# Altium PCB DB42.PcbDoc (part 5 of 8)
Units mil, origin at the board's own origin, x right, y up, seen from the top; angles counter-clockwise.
Board outline 3236.22 x 4456.69 mil, 8 copper layers (Top Layer, MidLayer1, MidLayer2, GND-Layer5, MidLayer3, VCC, MidLayer4, Bottom Layer), stack 62.194 mil thick; 214 components, 470 nets, 1802 pads, 1663 vias.
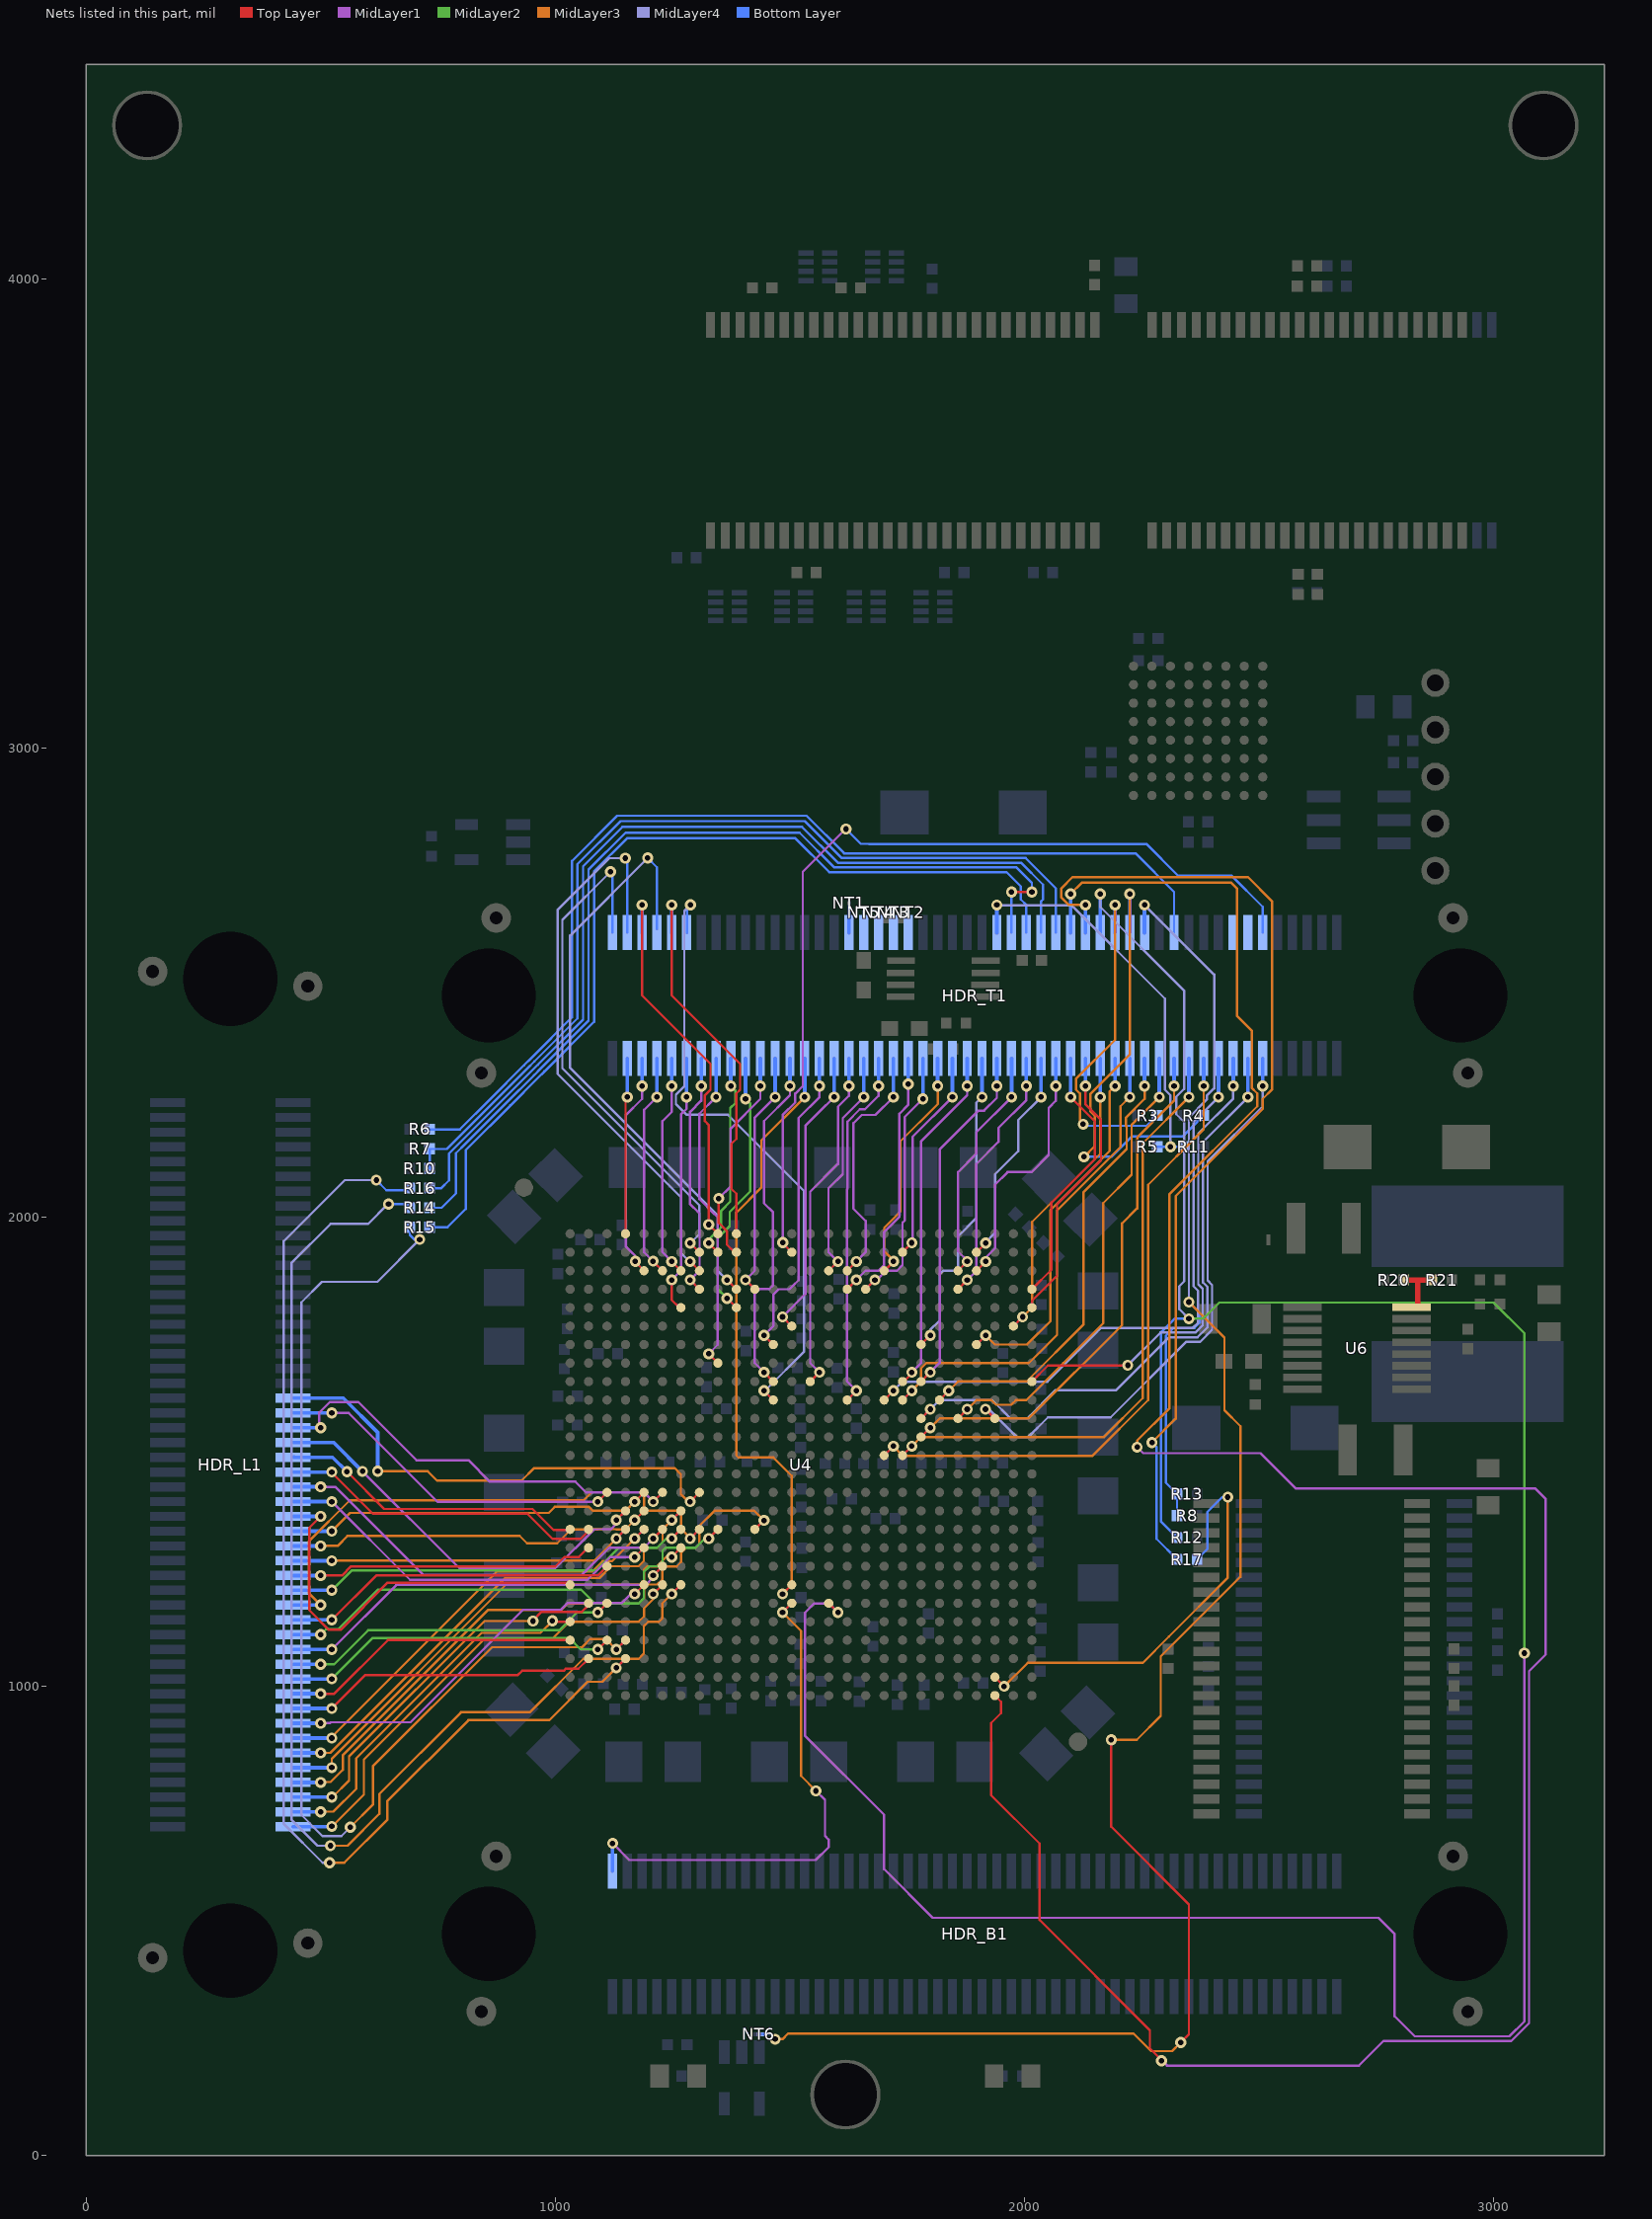
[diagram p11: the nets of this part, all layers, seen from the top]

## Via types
v1: diameter 23.62, hole 11.81, Top Layer to Bottom Layer, 1081 vias
v2: diameter 23.62, hole 11.81, Top Layer to Bottom Layer, tented both sides, 466 vias
v3: diameter 27.56, hole 15.75, Top Layer to Bottom Layer, 116 vias

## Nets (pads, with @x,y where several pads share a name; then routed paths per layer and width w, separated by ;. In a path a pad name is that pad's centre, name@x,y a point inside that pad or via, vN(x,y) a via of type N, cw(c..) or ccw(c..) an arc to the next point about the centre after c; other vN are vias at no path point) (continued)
EXTEND_B20: HDR_L1.42 U4.R8 | length 1060.6
  Top Layer w5: v1(1287.4,1393.7) U4.R8@1307.09,1413.39
  MidLayer3 w5: v2(621.34,1458.59) 727.86,1458.59 747.84,1438.61 928.18,1438.61 954.75,1465.18 1254.21,1465.18 1267.5,1451.89 1267.5,1409.73 1283.53,1393.7 v1(1287.4,1393.7)
  Bottom Layer w7.87: HDR_L1.42@440.94,1614.17 548.1,1614.17 621.34,1540.93 v2(621.34,1458.59)
EXTEND_B21: HDR_L1.44 U4.R3 | length 754.7
  Top Layer w5: v1(1090.55,1393.7) U4.R3@1110.24,1413.39
  MidLayer1 w5: v2(523.62,1582.68) 559.49,1582.68 748.86,1393.31 v1@1089.37,1393.31
  Bottom Layer w7.87: HDR_L1.44@440.94,1582.67 v2(523.62,1582.68)
EXTEND_B22: HDR_L1.46 U4.R6 | length 928.4
  Top Layer w5: v1(1208.66,1393.7) U4.R6@1228.35,1413.39
  MidLayer1 w5: v2@501.17,1553.15 496.82,1557.5 496.82,1583.43 519.29,1605.91 580.01,1605.91 704.01,1481.9 814.75,1481.9 860.53,1436.13 1043,1436.13 1065.75,1413.39 1188.18,1413.39 1188.58,1413.78 v1(1208.66,1393.7)
  Bottom Layer w7.87: HDR_L1.46@440.94,1551.18 v2(500,1551.18)
EXTEND_B23: HDR_L1.48 U4.T4 | length 875.1
  Top Layer w5: v1(1129.92,1354.33) U4.T4@1149.61,1374.02
  MidLayer1 w5: v2(589.03,1458.19) 795.58,1251.65 999.88,1251.65 1083.11,1334.87 1118.57,1334.87 1129.92,1346.23 v1(1129.92,1354.33)
  Bottom Layer w7.87: HDR_L1.48@440.94,1519.68 523.62,1519.68 527.54,1519.68 v2(589.03,1458.19)
EXTEND_B24: HDR_L1.50 U4.U1 | length 654.8
  Top Layer w5: v2(555.93,1457.41) 635.25,1378.09 951.24,1378.09 996.03,1333.3 U4.U1@1031.1,1333.3
  Bottom Layer w7.87: HDR_L1.50@440.94,1488.19 HDR_L1.50@442.07,1488.19 ; HDR_L1.50@442.41,1488.53 HDR_L1.50@442.07,1488.19 ; v2(555.93,1457.41) 525.15,1488.19 HDR_L1.50@442.07,1488.19
EXTEND_B25: HDR_L1.52 U4.U2 | length 696.2
  Top Layer w5: v2@523,1456.07 611.34,1367.72 940.73,1367.72 994.06,1314.38 1053.95,1314.38 U4.U2@1070.87,1331.3
  Bottom Layer w7.87: HDR_L1.52@440.94,1456.69 v2(523.62,1456.69)
EXTEND_B26: HDR_L1.54 U4.U6 | length 905.1
  Top Layer w5: v1(1208.66,1314.96) U4.U6@1228.35,1334.65
  MidLayer1 w5: v2(500,1425.2) 531.11,1425.2 718.48,1237.83 1057.23,1237.83 1114.87,1295.47 1189.09,1295.47 1208.58,1314.96 v1(1208.66,1314.96)
  Bottom Layer w7.87: HDR_L1.54@440.94,1425.19 v2(500,1425.2)
EXTEND_B27: HDR_L1.56 U4.V5 | length 846.1
  Top Layer w5: v1(1169.29,1275.59) U4.V5@1188.98,1295.28
  MidLayer1 w5: v2(523.62,1393.7) v2@523.75,1393.7 ; v2@523.75,1393.58 690.32,1227.01 1068.58,1227.01 1117.17,1275.59 v1(1169.29,1275.59) v1@1169.29,1274.8
  Bottom Layer w7.87: HDR_L1.56@440.94,1393.7 v2(523.62,1393.7)
EXTEND_B28: HDR_L1.58 U4.Y1 | length 885.8
  Top Layer w5: v2(500,1362.21) 475.56,1337.76 475.56,1162.3 517.32,1120.54 542.18,1120.54 642.65,1221.01 1027.03,1221.01 U4.Y1@1031.5,1216.54
  Bottom Layer w7.87: HDR_L1.58@440.94,1362.2 v2(500,1362.21)
EXTEND_B29: HDR_L1.60 U4.R5 | length 790.8
  Top Layer w5: v1(1169.29,1393.7) U4.R5@1188.98,1413.39
  MidLayer3 w5: v2@522,1331 523.62,1331 562.35,1369.73 985.97,1369.73 998.76,1382.52 1071.93,1382.52 1080.43,1374.02 1149.61,1374.02 v1(1169.29,1393.7)
  Bottom Layer w7.87: HDR_L1.60@440.94,1330.71 v2(523.62,1330.71)
EXTEND_B30: HDR_L1.62 U4.T5 | length 791.5
  Top Layer w5: v1(1169.29,1354.33) U4.T5@1188.98,1374.02
  MidLayer3 w5: v2@501.17,1299.41 535.83,1299.41 556.94,1320.53 923.98,1320.53 939.72,1304.78 1003.78,1304.78 1033.25,1334.25 1090.07,1334.25 1090.84,1335.02 1129.63,1335.02 1130.38,1334.26 1149.23,1334.26 v1(1169.29,1354.33)
  Bottom Layer w7.87: HDR_L1.62@440.94,1299.21 v2(500,1299.21)
EXTEND_B31: HDR_L1.64 U4.U4 | length 740.1
  Top Layer w5: v1(1129.92,1314.96) U4.U4@1149.61,1334.65
  MidLayer3 w5: v2(523.62,1267.72) v2@525.2,1267.72 ; v2@523.62,1269.29 524.41,1268.5 v2@525.2,1267.72 ; v1@1131.1,1315.75 1130.12,1314.76 1083.07,1267.72 v2@525.2,1267.72
  Bottom Layer w7.87: HDR_L1.64@440.94,1267.71 v2(523.62,1267.72)
EXTEND_B32: HDR_L1.66 U4.V2 | length 655.6
  Top Layer w5: v2@501.58,1237.8 v2(500,1236.22) 545.28,1236.22 564.73,1255.67 ; 564.82,1255.58 999.63,1255.58 1019.42,1275.38 1050.01,1275.38 U4.V2@1069.91,1295.28
  Bottom Layer w7.87: HDR_L1.66@440.94,1236.22 v2(500,1236.22)
EXTEND_B33: HDR_L1.68 U4.U7 | length 880.6
  Top Layer w5: v1(1248.03,1314.96) U4.U7@1267.72,1334.65
  MidLayer2 w5: v2(523.62,1204.72) 565.63,1246.73 1086.34,1246.73 1134.69,1295.08 1216.67,1295.08 1236.55,1314.96 v1(1248.03,1314.96)
  Bottom Layer w7.87: HDR_L1.68@440.94,1204.72 v2(523.62,1204.72)
EXTEND_B34: HDR_L1.70 U4.U8 | length 1160.6
  Top Layer w5: v1(1287.4,1314.96) U4.U8@1307.09,1334.65
  MidLayer3 w5: v2@499.2,1174.03 473.98,1199.25 473.98,1308.47 562.05,1396.54 1060.3,1396.54 1077.48,1413.72 1179.53,1413.72 1189.09,1404.17 1189.09,1380.18 1195,1374.27 1258.83,1374.27 1267.89,1365.21 1267.89,1335.66 v1@1287.4,1316.15
  Bottom Layer w7.87: HDR_L1.70@440.94,1173.23 v2(500,1173.23)
EXTEND_B35: HDR_L1.72 U4.W3 | length 716.6
  Top Layer w5: v2(523.62,1141.73) 618.11,1236.22 1090.55,1236.22 U4.W3@1110.24,1255.91
  Bottom Layer w7.87: HDR_L1.72@440.94,1141.73 v2(523.62,1141.73)
EXTEND_B36: HDR_L1.74 U4.U9 | length 1069.3
  Top Layer w5: v1(1326.77,1314.96) U4.U9@1346.46,1334.65
  MidLayer2 w5: v2(500,1110.24) 511.48,1121.72 537.4,1121.72 622.03,1206.34 1054.29,1206.34 1083.75,1176.88 1178.06,1176.88 1188.7,1187.52 1188.7,1243.86 1200.91,1256.07 1218.25,1256.07 1228.49,1266.32 1228.49,1289.17 1234.8,1295.47 1299.02,1295.47 1318.51,1314.96 v1(1326.77,1314.96)
  Bottom Layer w7.87: HDR_L1.74@440.94,1110.23 v2(500,1110.24)
EXTEND_B37: HDR_L1.76 U4.W6 | length 863.1
  Top Layer w5: v1(1208.66,1236.22) U4.W6@1228.35,1255.91
  MidLayer1 w5: v2(523.62,1078.74) 661.16,1216.28 1192.64,1216.28 1208.66,1232.3 v1(1208.66,1236.22)
  Bottom Layer w7.87: HDR_L1.76@440.94,1078.74 v2(523.62,1078.74)
EXTEND_B38: HDR_L1.78 U4.AA3 | length 723.1
  Top Layer w5: v1(1090.55,1157.48) U4.AA3@1110.24,1177.17
  MidLayer2 w5: v2(500,1047.25) 528.68,1047.25 600.72,1119.29 1008.57,1119.29 1046.77,1157.48 v1(1090.55,1157.48)
  Bottom Layer w7.87: HDR_L1.78@440.94,1047.24 v2(500,1047.25)
EXTEND_B39: HDR_L1.80 U4.AC3 | length 723.7
  Top Layer w5: v1(1090.55,1078.74) U4.AC3@1110.24,1098.42
  MidLayer2 w5: v2(523.62,1015.75) 610.94,1103.06 1029.54,1103.06 1053.86,1078.74 v1(1090.55,1078.74)
  Bottom Layer w7.87: HDR_L1.80@440.94,1015.74 v2(523.62,1015.75)
EXTEND_B40: HDR_L1.82 U4.AC1 | length 638.2
  Top Layer w5: v2(500,984.25) 528.74,984.25 643.19,1098.7 1003.94,1098.7 ; 1003.7,1098.42 U4.AC1@1031.5,1098.42
  Bottom Layer w7.87: HDR_L1.82@440.94,984.25 v2(500,984.25)
EXTEND_B41: HDR_L1.84 U4.AD2 | length 673
  Top Layer w5: v2(523.62,952.75) 595.17,1024.3 920.13,1024.3 929.02,1033.2 1017.85,1033.2 1022.17,1037.52 1049.29,1037.52 1070.04,1058.27 U4.AD2@1070.04,1058.5
  Bottom Layer w7.87: HDR_L1.84@440.94,952.75 v2(523.62,952.75)
EXTEND_B42: HDR_L1.86 U4.Y5 | length 873.2
  Top Layer w5: v1(1169.29,1196.85) U4.Y5@1188.98,1216.54
  MidLayer1 w5: v2(500,921.26) 499.26,922 500,922 520.28,922 521.82,923.54 ; 520.47,923.54 521.82,923.54 ; v1(1169.29,1196.85) 1161,1196.85 1141.42,1177.27 1025.58,1177.27 1011.79,1163.48 931.42,1163.48 691.47,923.54 521.82,923.54
  Bottom Layer w7.87: HDR_L1.86@440.94,921.26 v2(500,921.26)
EXTEND_B43: HDR_L1.88 U4.U5 | length 933.4
  Top Layer w5: v1(1169.29,1314.96) U4.U5@1188.98,1334.65
  MidLayer3 w5: v2@522,891 522.19,891.19 875.58,1244.58 1078.75,1244.58 1101.1,1266.93 1121.26,1266.93 v1(1169.29,1314.96)
  Bottom Layer w7.87: HDR_L1.88@440.94,889.76 v2(523.62,889.76)
EXTEND_B44: HDR_L1.90 U4.T7 | length 1070.2
  Top Layer w5: v1(1248.03,1354.33) U4.T7@1267.72,1374.02
  MidLayer3 w5: v2(500,858.27) 520.27,858.27 892.83,1230.83 1093.57,1230.83 1118.81,1256.07 1177.67,1256.07 1188.7,1267.1 1188.7,1289.17 1194.81,1295.28 1217.72,1295.28 1223.92,1301.48 1228.72,1306.28 1228.72,1335.02 v1(1248.03,1354.33)
  Bottom Layer w7.87: HDR_L1.90@440.94,858.26 v2(500,858.27)
EXTEND_B45: HDR_L1.92 U4.V7 | length 1045
  Top Layer w5: v1(1248.03,1275.59) U4.V7@1267.72,1295.28
  MidLayer3 w5: v2(523.62,826.77) 523.62,845.62 894.54,1216.54 1178.71,1216.54 1189.09,1226.92 1189.09,1249.37 1195.25,1255.53 1216.16,1255.53 1236.22,1275.59 v1(1248.03,1275.59)
  Bottom Layer w7.87: HDR_L1.92@440.94,826.77 v2(523.62,826.77)
EXTEND_B46: HDR_L1.94 U4.U11 | length 1358.1
  Top Layer w5: U4.U11@1425.2,1334.65 v1@1445.28,1354.72
  MidLayer3 w5: v2@500,796 521,796 546.84,821.84 546.84,852.84 857.09,1163.09 1012.54,1163.09 1026.33,1176.88 1179.24,1176.88 1189.09,1186.73 1189.09,1209.19 1196.81,1216.91 1217.32,1216.91 1227.97,1227.56 1227.97,1248.84 1231.92,1252.78 1234.66,1255.53 1258.66,1255.53 1268.09,1264.96 1268.09,1284.23 1279.13,1295.28 1299.21,1295.28 1306.71,1302.77 1306.71,1341.75 1338.98,1374.02 1424.41,1374.02 v1(1444.88,1353.54)
  Bottom Layer w7.87: HDR_L1.94@440.94,795.27 v2(500,795.28)
EXTEND_B47: HDR_L1.96 U4.AA2 | length 832.6
  Top Layer w5: v1@951.51,1139.84 970.49,1158.82 1056.57,1158.82 1070.87,1173.11 U4.AA2@1070.87,1177.17
  MidLayer3 w5: v2(523.62,763.78) v2@523.62,764 ; v2@525,764 560.48,799.48 560.48,850.48 849.05,1139.05 v1(952.3,1139.05)
  Bottom Layer w7.87: HDR_L1.96@440.95,763.78 v2(523.62,763.78)
EXTEND_B48: HDR_L1.98 U4.AB1 | length 795.6
  Top Layer w5: v1@995.32,1137.8 U4.AB1@1031.5,1137.8
  MidLayer3 w5: v2(500,732.28) 500.72,733 527,733 575.62,781.62 575.62,846.62 842.84,1113.84 968.06,1113.84 v1(993.67,1139.45)
  Bottom Layer w7.87: HDR_L1.98@440.94,732.28 v2(500,732.28)
EXTEND_B49: HDR_L1.100 U4.Y6 | length 1061.2
  Top Layer w5: v1(1208.66,1196.85) U4.Y6@1228.35,1216.54
  MidLayer3 w5: v1@523.62,700.79 523.96,701.12 592.02,769.18 592.02,844.02 847.61,1099.61 991.73,1099.61 1029.92,1137.79 1177.56,1137.79 1188.98,1149.21 1188.98,1166.24 1208.66,1185.92 v1(1208.66,1196.85)
  Bottom Layer w7.87: HDR_L1.100@440.94,700.78 523.49,700.79 v1@523.62,700.79
  other v1: 523.49,701.59
EXTEND_C0: HDR_T1.89 U4.L24 | length 1260.8
  Top Layer w5: v1(1916.93,1590.55) 1936.61,1570.87 U4.L24@1937.01,1570.87
  MidLayer4 w5: v1@1917.32,1589.37 1925.2,1589.37 1983.07,1531.5 2008.27,1531.5 2050,1573.23 2183.47,1573.23 2344.24,1734 2374,1734 2400,1760 2400,1855.43 2390.39,1865.03 2390.39,2118.74 2507.87,2236.22 v2(2507.87,2279.53)
  Bottom Layer w7.87: v2(2507.87,2279.53) HDR_T1.89@2507.88,2338.58
EXTEND_C1: HDR_T1.87 U4.L20 | length 1340.8
  Top Layer w5: U4.L20@1779.53,1570.87 v1(1799.21,1590.55)
  MidLayer4 w5: v1(1799.21,1590.55) 1818.9,1610.24 1931.1,1610.24 1970.47,1570.87 2005.91,1570.87 2066.54,1631.5 2195.67,1631.5 2308.17,1744 2369,1744 2390,1765 2390,1851.28 2380.39,1860.89 2380.39,2159.92 v2(2476.38,2255.9)
  Bottom Layer w7.87: v2(2476.38,2255.9) HDR_T1.87@2476.38,2338.58
EXTEND_C2: HDR_T1.85 U4.J26 | length 1017.6
  Top Layer w5: U4.J26@2015.75,1649.61 2050,1683.86 2219.68,1683.86 v1(2220.08,1684.25)
  MidLayer4 w5: v1(2220.08,1684.25) 2289.83,1754 2364.14,1754 2380,1769.86 2380,1847.14 2370.39,1856.75 2370.39,2178.39 2444.88,2252.88 v2(2444.88,2279.53)
  Bottom Layer w7.87: v2(2444.88,2279.53) HDR_T1.85@2444.88,2338.58
EXTEND_C3: HDR_T1.83 U4.K18 | length 1327
  Top Layer w5: U4.K18@1700.79,1610.24 v1(1720.47,1629.92)
  MidLayer4 w5: v1(1720.47,1629.92) 1739.84,1649.28 2048.89,1649.28 2163.61,1764 2359,1764 2370,1775 2370,1843 2360.39,1852.61 2360.39,2202.92 v2(2413.38,2255.9)
  Bottom Layer w7.87: v2(2413.38,2255.9) HDR_T1.83@2413.39,2338.58
EXTEND_C4: HDR_T1.81 U4.N18 | length 1406.5
  Top Layer w5: U4.N18@1700.79,1492.13 v1(1720.47,1511.81)
  MidLayer3 w5: v1(1720.47,1511.81) 1741.34,1490.94 2144.49,1490.94 2263.78,1610.24 2263.78,2068.95 2381.89,2187.05 v2(2381.89,2279.53)
  Bottom Layer w7.87: v2(2381.89,2279.53) HDR_T1.81@2381.89,2338.58
EXTEND_C5: HDR_T1.79 U4.N19 | length 1327.5
  Top Layer w5: U4.N19@1740.16,1492.13 v1(1759.84,1511.81)
  MidLayer3 w5: v1(1759.84,1511.81) 1779.53,1531.5 2169.29,1531.5 2251.97,1614.17 2251.97,2157.48 v2(2350.39,2255.9)
  Bottom Layer w7.87: v2(2350.39,2255.9) HDR_T1.79@2350.4,2338.58
EXTEND_C6: HDR_T1.77 U4.M20 | length 1141.7
  Top Layer w5: U4.M20@1779.53,1531.5 v1(1799.21,1551.18)
  MidLayer3 w5: v1(1799.21,1551.18) 1818.9,1570.87 2008.75,1570.87 2208.1,1770.22 2208.1,1986.7 2240.16,2018.76 2240.16,2169.29 2318.89,2248.03 v2(2318.89,2279.53)
  Bottom Layer w7.87: v2(2318.89,2279.53) HDR_T1.77@2318.9,2338.58
EXTEND_C7: HDR_T1.75 U4.L22 | length 1016.2
  Top Layer w5: U4.L22@1858.27,1570.87 v1(1877.95,1590.55)
  MidLayer3 w5: v1(1877.95,1590.55) 1897.64,1610.24 1929.13,1610.24 1939.37,1600 1971.65,1600 1981.89,1610.24 2003.93,1610.24 2082.83,1689.13 2167.75,1774.05 2167.75,2029.99 2228.35,2090.59 2228.35,2196.85 v2(2287.4,2255.9)
  Bottom Layer w7.87: v2(2287.4,2255.9) HDR_T1.75@2287.4,2338.58
EXTEND_C8: HDR_T1.73 U4.K21 | length 995.5
  Top Layer w5: U4.K21@1818.9,1610.24 v1(1838.58,1629.92)
  MidLayer3 w5: v1(1838.58,1629.92) 1858.64,1649.98 2004.7,1649.98 2125.44,1770.72 2125.44,2052.62 2217.94,2145.12 2217.94,2194.32 ; 2216.54,2194.32 2216.54,2212.6 2255.9,2251.97 v2(2255.9,2279.53)
  Bottom Layer w7.87: v2(2255.9,2279.53) HDR_T1.73@2255.91,2338.58
EXTEND_C9: HDR_T1.71 U4.K19 | length 1057.1
  Top Layer w5: U4.K19@1740.16,1610.24 v1(1759.84,1629.92)
  MidLayer3 w5: v1(1759.84,1629.92) 1779.15,1649.23 1779.15,1677.58 1790.55,1688.98 2009.33,1688.98 2069.35,1749 2069.35,2014.25 2204.72,2149.62 2204.72,2236.22 v2(2224.41,2255.9)
  Bottom Layer w7.87: v2(2224.41,2255.9) HDR_T1.71@2224.41,2338.58
EXTEND_C10: HDR_T1.69 U4.G23 | length 811.9
  Top Layer w5: U4.G23@1897.64,1728.35 v1(1917.32,1748.03)
  MidLayer3 w5: v1(1917.32,1748.03) 1937.01,1728.35 2005.3,1728.35 2055.21,1778.25 2055.21,2014.74 2181.5,2141.02 2181.5,2268.11 v2(2192.91,2279.53)
  Bottom Layer w7.87: v2(2192.91,2279.53) HDR_T1.69@2192.91,2338.58
EXTEND_C11: HDR_T1.67 U4.F25 | length 647.5
  Top Layer w5: U4.F25@1976.38,1767.72 v1(1996.06,1787.4)
  MidLayer3 w5: v1(1996.06,1787.4) 2010.23,1801.56 2016.22,1807.55 2016.22,1990.14 2161.42,2135.34 v2(2161.42,2255.9)
  Bottom Layer w7.87: v2(2161.42,2255.9) HDR_T1.67@2161.42,2338.58
EXTEND_C12: HDR_T1.65 U4.E26 | length 605.3
  Top Layer w5: U4.E26@2015.75,1807.09 2015.75,1821.65 2069.38,1875.29 2069.38,2027.07 2163,2120.69 2163,2207.25 2129.57,2240.68 ; 2129.92,2241.76 v2(2129.92,2279.53)
  Bottom Layer w7.87: v2(2129.92,2279.53) HDR_T1.65@2129.92,2338.58
EXTEND_C13: HDR_T1.63 U4.D26 | length 569.1
  Top Layer w5: U4.D26@2015.75,1846.46 2057.31,1888.02 2057.31,2030.74 2150,2123.43 2150,2204.33 v2(2098.42,2255.9)
  Bottom Layer w7.87: v2(2098.42,2255.9) HDR_T1.63@2098.43,2338.58
EXTEND_C14: HDR_T1.61 U4.C23 | length 552.9
  Top Layer w5: U4.C23@1897.64,1885.83 v1(1917.32,1905.51)
  MidLayer1 w5: v1(1917.32,1905.51) 1917.32,1913.78 1937.38,1933.84 1937.38,2069.35 1963.95,2095.92 2015.23,2095.92 2051.64,2132.33 2051.64,2232.74 2066.93,2248.03 v2(2066.93,2279.53)
  Bottom Layer w7.87: v2(2066.93,2279.53) HDR_T1.61@2066.93,2338.58
EXTEND_C15: HDR_T1.59 U4.B23 | length 470.5
  Top Layer w5: U4.B23@1897.64,1925.2 v1(1917.32,1944.88)
  MidLayer4 w5: v1(1917.32,1944.88) 1917.32,1946.46 1937.01,1966.14 1937.01,2091 1986.7,2140.69 1986.7,2207.17 v2(2035.43,2255.9)
  Bottom Layer w7.87: v2(2035.43,2255.9) HDR_T1.59@2035.43,2338.58
EXTEND_C16: HDR_T1.57 U4.D22 | length 552.5
  Top Layer w5: U4.D22@1858.27,1846.46 v1(1877.95,1866.14)
  MidLayer1 w5: v1(1877.95,1866.14) 1897.26,1885.45 1897.26,2113.26 1944.35,2160.35 1944.35,2189.84 2003.93,2249.42 v2(2003.93,2279.53)
  Bottom Layer w7.87: v2(2003.93,2279.53) HDR_T1.57@2003.94,2338.58
EXTEND_C17: HDR_T1.55 U4.C22 | length 516.8
  Top Layer w5: U4.C22@1858.27,1885.83 v1(1877.95,1905.51)
  MidLayer1 w5: v1@1878.74,1905.91 1878.74,1906.3 1858.27,1926.77 1858.27,1985.83 1858.27,2096 1897,2134.73 1897,2180.47 ; 1897,2181 1897,2180.47 ; v2(1972.44,2255.9) 1897,2180.47
  Bottom Layer w7.87: v2(1972.44,2255.9) HDR_T1.55@1972.44,2338.58
EXTEND_C18: HDR_T1.53 U4.J20 | length 762.8
  Top Layer w5: U4.J20@1779.53,1649.61 v1(1799.21,1669.29)
  MidLayer1 w5: v1(1799.21,1669.29) 1819.27,1689.35 1819.27,2144.27 1902,2227 1913.94,2227 1940.94,2254 v2(1940.94,2279.53)
  Bottom Layer w7.87: v2(1940.94,2279.53) HDR_T1.53@1940.95,2338.58
EXTEND_C19: HDR_T1.51 U4.G20 | length 677.7
  Top Layer w5: U4.G20@1779.53,1728.35 v1(1799.21,1748.03)
  MidLayer4 w5: v1(1799.21,1748.03) 1799.21,1759.94 1818.9,1779.63 1818.9,1878.35 1826.38,1885.83 1849.61,1885.83 1858.27,1894.49 1858.27,1959 1897.04,1997.78 1897.04,2243.5 v2(1909.45,2255.9)
  Bottom Layer w7.87: v2(1909.45,2255.9) HDR_T1.51@1909.45,2338.58
EXTEND_C20: HDR_T1.49 U4.J19 | length 746.1
  Top Layer w5: U4.J19@1746.82,1654.06 1760.95,1668.19 v1@1766.51,1673.74
  MidLayer1 w5: v1(1759.84,1669.29) 1779.15,1688.6 1779.15,2161.05 1791.5,2173.4 1877.95,2259.84 v2(1877.95,2279.53)
  Bottom Layer w7.87: v2(1877.95,2279.53) HDR_T1.49@1877.95,2338.58
EXTEND_C21: HDR_T1.47 U4.B19 | length 455.9
  Top Layer w5: U4.B19@1740.16,1925.2 v1(1759.84,1945.28)
  MidLayer1 w5: v1@1761.42,1946.06 1761.42,2170.87 v2(1846.46,2255.9)
  Bottom Layer w7.87: v2(1846.46,2255.9) HDR_T1.47@1846.46,2338.58
EXTEND_C22: HDR_T1.45 U4.C18 | length 510.4
  Top Layer w5: U4.C18@1706.3,1887.8 1706.3,1890.55 v1@1720.87,1905.51
  MidLayer3 w5: v1@1720.87,1907.48 1700.98,1927.36 1700.98,1977.36 1735.43,2011.81 1735.43,2161.43 1815.18,2241.18 1815.18,2279.3 v2(1814.96,2279.53)
  Bottom Layer w7.87: v2(1814.96,2279.53) HDR_T1.45@1814.96,2338.58
  other v1: 1720.87,1905.91
EXTEND_C23: HDR_T1.43 U4.D17 | length 558.8
  Top Layer w5: U4.D17@1661.42,1846.46 v1(1681.1,1866.14)
  MidLayer1 w5: v1(1681.1,1866.14) 1685.04,1866.14 1704.72,1885.83 1728.35,1885.83 1740.18,1897.66 1740.18,1988.17 ; 1740.16,1988.19 1744.88,1992.91 1744.88,2213.38 v2(1783.46,2251.96)
  Bottom Layer w7.87: v2(1783.46,2251.96) HDR_T1.43@1783.47,2338.58
EXTEND_C24: HDR_T1.41 U4.D16 | length 561.9
  Top Layer w5: U4.D16@1622.05,1846.46 v1(1641.73,1866.14)
  MidLayer1 w5: v1(1641.73,1866.14) 1661.42,1885.83 1688.73,1885.83 1700.81,1897.91 1700.81,1968.52 1733.46,2001.18 1733.46,2047.64 1733.46,2220.46 1751.97,2238.97 v2@1751.97,2279.53
  Bottom Layer w7.87: v2@1751.97,2279.53 HDR_T1.41@1751.97,2338.58
  other v2: 1751.97,2283.46
EXTEND_C25: HDR_T1.39 U4.C16 | length 533
  Top Layer w5: U4.C16@1622.05,1885.83 v1(1641.73,1905.51)
  MidLayer1 w5: v1(1641.73,1905.51) 1661.42,1925.2 1661.42,1992.13 1635.43,2018.11 1635.43,2200.25 1653.12,2217.94 1682.5,2217.94 v2(1720.47,2255.9)
  MidLayer3 w5: v1@1640.55,1905.91 v1@1641.34,1905.91
  Bottom Layer w7.87: v2(1720.47,2255.9) HDR_T1.39@1720.47,2338.58
EXTEND_C26: HDR_T1.37 U4.K16 | length 779.3
  Top Layer w5: U4.K16@1622.05,1610.24 v1(1641.73,1629.92)
  MidLayer1 w5: 1621.61,1982.63 1622.05,1983.07 ; v1(1641.73,1629.92) 1622.05,1649.61 1622.05,1983.07 ; v2(1688.97,2279.53) 1688.98,2258.71 1660.01,2229.74 1649.18,2229.74 1622.83,2203.39 1622.83,2059.84 1622.05,2059.06 1622.05,1983.07
  Bottom Layer w7.87: v2(1688.97,2279.53) HDR_T1.37@1688.98,2338.58
EXTEND_C27: HDR_T1.35 U4.C15 | length 500.4
  Top Layer w5: U4.C15@1582.68,1885.83 v1(1602.36,1905.51)
  MidLayer1 w5: v1(1602.36,1905.51) 1582.3,1925.57 1582.3,2061.44 1612.6,2091.73 1612.6,2211.02 v2(1657.48,2255.9)
  Bottom Layer w7.87: v2(1657.48,2255.9) HDR_T1.35@1657.48,2338.58
EXTEND_C28: HDR_T1.33 U4.J14 | length 739.5
  Top Layer w5: U4.J14@1543.31,1649.61 v1(1562.99,1669.29)
  MidLayer1 w5: v1(1562.99,1669.29) 1543.31,1688.98 1543.31,2054.33 1602.36,2113.39 1602.36,2235.07 1625.98,2258.69 v2(1625.98,2279.53)
  Bottom Layer w7.87: v2(1625.98,2279.53) HDR_T1.33@1625.99,2338.58
EXTEND_C29: HDR_T1.31 U4.F13 | length 624.8
  Top Layer w5: v1(1484.25,1787.4) U4.F13@1503.94,1767.72
  MidLayer1 w5: v1(1484.25,1787.4) 1533.07,1836.22 1533.07,2194.88 1576.77,2238.58 ; 1576.97,2238.39 v2(1594.49,2255.9)
  Bottom Layer w7.87: v2(1594.49,2255.9) HDR_T1.31@1594.49,2338.58
EXTEND_C30: HDR_T1.29 U4.G12 | length 680.9
  Top Layer w5: v1(1444.88,1748.03) U4.G12@1464.57,1728.35
  MidLayer1 w5: v1(1444.88,1748.03) 1464.57,1767.72 1464.57,1835.04 1475.98,1846.46 1499.21,1846.46 1506.46,1853.7 1518.5,1865.75 1518.5,2211.42 1562.99,2255.9 v2(1562.99,2279.53)
  Bottom Layer w7.87: v2(1562.99,2279.53) HDR_T1.29@1562.99,2338.58
EXTEND_C31: HDR_T1.27 U4.Y13 | length 1330.5
  Top Layer w5: v1(1484.25,1196.85) U4.Y13@1503.94,1216.54
  MidLayer3 w5: v1(1484.25,1196.85) 1503.94,1216.54 1503.94,1448.82 1464.57,1488.19 1389.76,1488.19 1386.2,1491.75 1386.2,2009.85 1439.13,2062.79 1439.13,2163.54 v2(1531.5,2255.9)
  Bottom Layer w7.87: v2(1531.5,2255.9) HDR_T1.27@1531.5,2338.58
EXTEND_C32: HDR_T1.25 U4.J12 | length 764.3
  Top Layer w5: v1(1444.88,1669.29) U4.J12@1464.57,1649.61
  MidLayer1 w5: v1(1444.88,1669.29) 1424.82,1689.35 1424.82,1835.45 1436.2,1846.83 1456.28,1846.83 1464.19,1854.74 1464.19,2010.22 1444.88,2029.53 1444.88,2204.72 1500,2259.84 v2(1500,2279.53)
  Bottom Layer w7.87: v2(1500,2279.53) HDR_T1.25@1500,2338.58
EXTEND_C33: HDR_T1.23 U4.D11 | length 526.4
  Top Layer w5: v1(1405.51,1866.14) U4.D11@1425.2,1846.46
  MidLayer1 w5: v1(1405.51,1866.14) 1425.2,1885.83 1425.2,2212.6 v2(1468.5,2255.9)
  Bottom Layer w7.87: v2(1468.5,2255.9) HDR_T1.23@1468.5,2338.58
EXTEND_C34: HDR_T1.21 U4.B10 | length 466.1
  Top Layer w5: v1(1348.43,2039.76) 1348.43,1987.83 1365.75,1970.5 1365.75,1941.73 1382.28,1925.2 U4.B10@1385.83,1925.2
  MidLayer1 w5: v1@1349.21,2040.94 1373.62,2065.35 1373.62,2188.58 1437.01,2251.97 v2(1437.01,2279.53)
  Bottom Layer w7.87: v2(1437.01,2279.53) HDR_T1.21@1437.01,2338.58
EXTEND_C35: HDR_T1.19 U4.E10 | length 577
  Top Layer w5: v1(1366.14,1826.77) U4.E10@1385.83,1807.09
  MidLayer2 w5: v1(1366.14,1826.77) 1346.26,1846.65 1346.26,1955.31 1371.65,1980.71 1371.65,2011.02 1415.75,2055.12 1415.75,2241.73 v2(1405.51,2251.97)
  Bottom Layer w7.87: v2@1405.51,2255.9 HDR_T1.19@1405.51,2338.58
EXTEND_C36: HDR_T1.17 U4.B9 | length 449.3
  Top Layer w5: v1(1326.77,1944.88) U4.B9@1346.46,1925.2
  MidLayer2 w5: v1(1326.77,1944.88) 1326.77,1951.57 1353.54,1978.35 1353.54,2013.78 1372.83,2033.07 1372.83,2232.28 1383.86,2243.31 1383.86,2269.68 v2(1374.02,2279.53)
  Bottom Layer w7.87: v2(1374.02,2279.53) HDR_T1.17@1374.02,2338.58
EXTEND_C37: HDR_T1.15 U4.H9 | length 696.7
  Top Layer w5: v1(1326.77,1708.66) U4.H9@1346.46,1688.98
  MidLayer1 w5: v1(1326.77,1708.66) 1346.08,1727.97 1346.08,1999.98 1339.37,2006.69 ; 1339.17,2006.5 1307.09,2038.58 1307.09,2220.47 v2(1342.52,2255.9)
  Bottom Layer w7.87: v2(1342.52,2255.9) HDR_T1.15@1342.52,2338.58
EXTEND_C38: HDR_T1.13 U4.D8 | length 526.8
  Top Layer w5: v1(1287.4,1866.14) U4.D8@1307.09,1846.46
  MidLayer1 w5: v1(1287.4,1866.14) 1307.46,1886.2 1307.46,2007.89 1303.94,2011.42 ; 1303.74,2011.22 1287.4,2027.56 1287.4,2224.41 1311.02,2248.03 v2(1311.02,2279.53)
  Bottom Layer w7.87: v2(1311.02,2279.53) HDR_T1.13@1311.02,2338.58
EXTEND_C39: HDR_T1.11 U4.E7 | length 554.8
  Top Layer w5: v1(1248.03,1866.14) 1248.03,1823.23 1264.17,1807.09 U4.E7@1267.72,1807.09
  MidLayer1 w5: v1(1248.03,1866.14) 1267.72,1885.83 1267.72,2218.87 1279.53,2230.68 v2(1279.53,2255.9)
  Bottom Layer w7.87: v2(1279.53,2255.9) HDR_T1.11@1279.53,2338.58
EXTEND_C40: HDR_T1.12 U4.K12 | length 1334.6
  Top Layer w5: v1(1444.88,1629.92) U4.K12@1464.57,1610.24
  MidLayer4 w5: v2(1288.19,2665.75) 1274.8,2652.36 1274.8,2278.74 1257.09,2261.02 1257.09,2240.94 1279.89,2218.14 1368.11,2218.14 1529.92,2056.33 1529.92,1712.99 1451.18,1634.25 v1@1449.21,1634.25
  Bottom Layer w5: HDR_T1.12@1280.31,2605.91 1280.31,2606.3 1280.31,2657.87 v2(1288.19,2665.75)
EXTEND_C41: HDR_T1.9 U4.C7 | length 477.2
  Top Layer w5: v1(1248.03,1905.51) U4.C7@1267.72,1885.83
  MidLayer1 w5: v1(1248.03,1905.51) 1228.35,1925.2 1228.35,2204.72 1248.03,2224.41 v2(1248.03,2279.53)
  Bottom Layer w7.87: v2(1248.03,2279.53) HDR_T1.9@1248.03,2338.58
EXTEND_C42: HDR_T1.10 U4.A10 | length 831.9
  Top Layer w5: v2(1248.03,2665.35) 1248.03,2472.44 1393.7,2326.78 1393.7,2271.65 1385.83,2263.78 1385.83,2166.96 1375.59,2156.72 1375.59,2060.24 1385.83,2050 U4.A10@1385.83,1964.57
  Bottom Layer w7.87: HDR_T1.10@1248.03,2606.3 v2(1248.03,2665.35)
EXTEND_C43: HDR_T1.7 U4.C6 | length 480.2
  Top Layer w5: v1@1208.66,1905.51 U4.C6@1228.35,1885.83
  MidLayer1 w5: v1@1208.66,1905.51 1208.2,1905.97 1189.35,1924.82 1189.35,2228.72 v2(1216.54,2255.9)
  Bottom Layer w7.87: v2(1216.54,2255.9) HDR_T1.7@1216.54,2338.58
  other v1: 1208.4,1906.17
EXTEND_C44: HDR_T1.8 U4.D10 | length 1295.1
  Top Layer w5: v1(1366.14,1866.14) U4.D10@1385.83,1846.46
  MidLayer4 w5: v1(1196.85,2765.35) 1197.24,2764.96 1196.85,2764.96 1196.46,2764.96 1031.5,2600 1031.5,2318.11 1346.46,2003.15 1346.46,1885.43 1365.94,1865.95 v1@1366.14,1865.75
  Bottom Layer w5: v1(1196.85,2765.35) 1216.54,2745.67 HDR_T1.8@1216.54,2613.78
EXTEND_C45: HDR_T1.5 U4.C5 | length 483
  Top Layer w5: v1@1169.68,1905.12 U4.C5@1188.98,1885.83
  MidLayer1 w5: v1(1170.47,1905.91) 1169.39,1906.99 1169.39,1918.4 1164.55,1923.25 1149.98,1937.82 1149.98,1945.34 1149.98,2216.91 1185.04,2251.97 v2(1185.04,2279.53)
  Bottom Layer w7.87: v2(1185.04,2279.53) HDR_T1.5@1185.04,2338.58
EXTEND_C46: HDR_T1.6 U4.A9 | length 895.5
  Top Layer w5: v2(1185.04,2665.35) 1185.04,2472.44 1330.71,2326.77 1330.71,2271.65 1318.9,2259.84 1318.9,2204.72 1326.77,2196.85 v1(1326.77,1984.25) U4.A9@1346.46,1964.57
  Bottom Layer w7.87: HDR_T1.6@1185.04,2606.3 v2(1185.04,2665.35) HDR_T1.6@1185.04,2606.3
EXTEND_C47: HDR_T1.3 U4.A4 | length 375.6
  Top Layer w5: U4.A4@1149.61,1964.57 1149.61,2251.97 v2(1153.54,2255.9)
  Bottom Layer w7.87: v2(1153.54,2255.9) HDR_T1.3@1153.54,2338.58
EXTEND_C48: HDR_T1.4 U4.C8 | length 1242.8
  Top Layer w5: v1(1287.4,1905.51) U4.C8@1307.09,1885.83
  MidLayer4 w5: v1(1149.21,2764.96) 1114.96,2764.96 1004.72,2654.72 1004.72,2305.51 1267.72,2042.52 1267.72,1923.62 1273.86,1917.48 v1@1284.93,1906.41
  Bottom Layer w5: v1(1149.21,2764.96) 1153.54,2760.63 HDR_T1.4@1153.54,2606.3
EXTEND_C49: HDR_T1.2 U4.B8 | length 1116.2
  Top Layer w5: v1(1287.4,1944.88) U4.B8@1307.09,1925.2
  MidLayer4 w5: v1(1117.72,2736.22) 1014.96,2633.46 1014.96,2317.32 1307.09,2025.2 1307.09,1963.78 v1@1288.19,1944.88
  Bottom Layer w5: HDR_T1.2@1122.05,2606.3 v1@1122.05,2731.89
FB: R20.2 R21.1 U6.8 | length 120.2
  Top Layer w7.87: U6.8@2842.51,1807.09 U6.8@2842.51,1808.25
  Top Layer w11.81: R20.2@2808.58,1866.14 2838.58,1866.14 ; U6.8@2838.58,1807.09 2838.58,1808.25 2838.58,1866.14 ; R21.1@2868.58,1866.14 2838.58,1866.14
FPGA_CCLK: HDR_T1.66 R17.1 | length 2147.2
  MidLayer3 w5: v2(2129.92,2665.35) 2094.49,2665.35 2078.74,2681.1 2078.74,2700.79 2102.36,2724.41 2476.38,2724.41 2527.56,2673.23 2527.56,2271.65 2507.87,2251.97 2507.87,2230.39 2322.33,2044.84 2322.33,1570.36 v1(2271.65,1519.68)
  Bottom Layer w5: v1(2271.65,1519.68) 2281.34,1510 2281.34,1314.39 R17.1@2325.28,1270.45
  Bottom Layer w7.87: HDR_T1.66@2129.92,2606.3 v2(2129.92,2665.35)
FPGA_CCLK#: R17.2 U4.AE24 | length 939.7
  Top Layer w5: U4.AE24@1936.57,1019.68 U4.AE24@1937.01,1019.68 v1(1956.69,1000)
  MidLayer3 w5: v1(1956.69,1000) 2006.69,1050 2251.97,1050 2307.84,1105.87 2433.4,1231.43 v1(2433.4,1403.2)
  Bottom Layer w5: R17.2@2367.64,1270.45 2390,1292.81 2390,1371.85 2421.35,1403.2 v1(2433.4,1403.2)
FPGA_CLK: HDR_B1.2 U4.AA13 | length 1114.4
  Top Layer w5: v1(1484.25,1157.48) U4.AA13@1503.94,1177.17
  MidLayer1 w5: v2(1122.05,665.35) 1157.48,629.92 1555.12,629.92 1582.68,657.48 1582.68,673.23 1574.8,681.1 1574.8,757.87 v1(1555.51,777.17)
  MidLayer3 w5: v1(1484.25,1157.48) 1523.62,1118.11 1523.62,809.06 v1(1555.51,777.17)
  Bottom Layer w7.87: HDR_B1.2@1122.05,606.3 v2(1122.05,665.35)
FPGA_CLK1: HDR_T1.90 U4.B13 | length 1978.2
  Top Layer w5: v1@1484.25,1944.88 U4.B13@1503.94,1925.2
  MidLayer1 w5: v1(1484.65,1945.67) 1484.65,2217.72 1511.42,2244.49 1511.42,2263.39 1527.56,2279.53 1527.56,2736.22 v1@1619.68,2828.35
  Bottom Layer w5: v1(1619.68,2827.17) 1651.18,2795.67 1669.29,2795.67 ; 1669.29,2795.28 2259.84,2795.28 2326.77,2728.35 2440.94,2728.35 2507.87,2661.42 HDR_T1.90@2507.88,2606.3
FPGA_DIN: HDR_T1.64 U4.AF24 | length 5581.6
  Top Layer w5: U4.AF24@1937.01,979.92 1950,966.93 1950,943 1929,922 1929,768 2032,665 2032,502.32 2267.32,267 2267.32,228.35 v1@2292.13,203.54
  MidLayer1 w5: v1(2240.16,1509.84) 2253,1497 2503,1497 2578,1422 3088,1422 3111,1399 3111,1068 3075.4,1032.4 3075.4,281.86 3037.54,244 2765.26,244 2712.99,191.73 2303.94,191.73 2292.91,202.76 v1@2292.13,203.54
  MidLayer3 w5: v2(2098.42,2688.98) 2122.05,2712.6 2440.94,2712.6 2452.76,2700.79 2452.76,2429.13 2484.25,2397.64 2484.25,2275.59 2496.06,2263.78 2496.06,2236.29 2309.21,2049.44 2309.21,1592.68 2240.16,1523.62 v1(2240.16,1509.84)
  Bottom Layer w7.87: v2(2098.42,2688.98) HDR_T1.64@2098.43,2606.3
  other v1: 2292.13,201.97
FPGA_DONE: HDR_T1.74 NT6.2 R8.1 R13.1 | length 4291.3
  Top Layer w5: v1(2185.04,885.83) 2185.04,700.79 2350.39,535.43 2350.39,258.27 v1(2333.07,240.94)
  MidLayer3 w5: v1(1468.5,248.03) 1484.25,248.03 1496.06,259.84 2232.68,259.84 2270.08,222.44 2314.57,222.44 v1(2333.07,240.94) ; v1@2183.86,886.22 v1@2185.04,886.22 ; v1(2185.04,885.83) v1@2185.04,886.22 ; v1(2350.39,1818.9) 2426.3,1742.99 2426.3,1588.19 2460.24,1554.25 2460.24,1233.71 2290.31,1063.78 2290.31,937.16 2239.37,886.22 v1@2185.04,886.22
  MidLayer4 w5: v2(2255.9,2665.35) 2404.33,2516.93 2404.33,2274.41 2388.58,2258.66 2388.58,2250.39 2350.39,2212.2 v1(2350.39,1818.9)
  Bottom Layer w5: NT6.2@1440.94,258.86 1457.68,258.86 v1(1468.5,248.03) ; R8.1@2325.28,1363.63 R13.1@2325.28,1410.21 2301.34,1434.15 2301.34,1747.44 2318,1764.1 2362.62,1764.1 2374.02,1775.5 2374.02,1795.28 v1(2350.39,1818.9)
  Bottom Layer w7.87: HDR_T1.74@2255.91,2606.3 v2(2255.9,2665.35)
FPGA_ID0: HDR_T1.42 NT2.1
FPGA_ID1: HDR_T1.40 NT3.1
FPGA_ID2: HDR_T1.38 NT4.1
FPGA_ID3: HDR_T1.36 NT5.1
FPGA_INIT: HDR_T1.68 R12.1 U4.AA15 | length 6193.8
  Top Layer w5: U4.AA15@1582.68,1177.17 v1(1602.36,1157.48)
  MidLayer1 w5: v1(1602.36,1157.48) 1583.05,1176.79 1551.99,1176.79 1531.89,1156.69 1531.89,895.08 1700.86,726.11 1700.86,610.17 1804.29,506.73 2754.27,506.73 2789.1,471.9 2789.1,296.9 2832,254 3033.4,254 3065.4,286 v1(3065.4,1070.7)
  MidLayer2 w5: v1(2350.39,1783.46) 2380.46,1783.46 2415,1818 3000,1818 3065.4,1752.6 v1(3065.4,1070.7)
  MidLayer4 w5: v2(2161.42,2688.98) 2161.42,2661.42 2340.16,2482.68 2340.16,2273.23 2323.62,2256.69 2323.62,2219.29 2340.39,2202.52 2340.39,1863.31 2329.8,1852.71 2329.8,1804.06 v1(2350.39,1783.46)
  Bottom Layer w5: R12.1@2325.28,1317.04 2291.34,1350.97 2291.34,1754.94 2319.86,1783.46 v1(2350.39,1783.46)
  Bottom Layer w7.87: HDR_T1.68@2161.42,2606.3 v2(2161.42,2688.98)
FPGA_INSTALLED: HDR_T1.34 NT1.1 | length 55.2
  Bottom Layer w7.87: HDR_T1.34@1625.99,2606.3 NT1.1@1625.98,2661.42
FPGA_M0: HDR_T1.60 R16.1 | length 2005.7
  Bottom Layer w5: R16.1@732.11,2061.94 757.15,2061.94 773.42,2078.21 773.42,2135.58 804.56,2166.71 884.14,2246.28 947.59,2309.74 962.63,2324.78 1059.06,2421.21 1059.06,2747.64 1142.91,2831.5 1525.98,2831.5 1602.2,2755.28 1992.76,2755.28 2039.37,2708.66 2039.37,2677.17 2035.43,2673.23 HDR_T1.60@2035.43,2606.3
FPGA_M0#: R16.2 U4.AD4 | length 2541.3
  Top Layer w5: v1(1129.92,1039.37) U4.AD4@1149.61,1059.05
  MidLayer3 w5: v1(518.57,623.86) 550.06,623.86 641.57,715.37 641.57,754.73 814.75,927.91 986.95,927.91 1068.62,1009.58 1100.14,1009.58 v1(1129.92,1039.37)
  MidLayer4 w5: v1(518.57,623.86) 503.92,623.86 421.26,706.51 421.26,1948.82 551.34,2078.9 v1(618.5,2078.9)
  Bottom Layer w5: v1(618.5,2078.9) 639.92,2057.48 685.29,2057.48 R16.2@689.74,2061.94
FPGA_M1: HDR_T1.58 R15.1 | length 2011.1
  Bottom Layer w5: R15.1@731.81,1978.35 R15.1@732.11,1978.35 769.99,1978.35 808.85,2017.2 808.85,2142.71 812.84,2146.71 904.14,2237.99 ; 904.14,2238 961.73,2295.6 976.77,2310.63 1082.68,2416.54 1082.68,2737.44 1152.72,2807.48 1511.47,2807.48 1583.68,2735.28 1961.57,2735.28 1992.13,2704.72 1992.13,2677.17 2003.94,2665.35 HDR_T1.58@2003.94,2606.3
FPGA_M1#: R15.2 U4.AC4 | length 2390.5
  Top Layer w5: v1(1129.92,1078.74) U4.AC4@1149.61,1098.42
  MidLayer3 w5: v1(562.85,699.62) 611.06,747.84 611.06,829.51 864.94,1083.38 1056.82,1083.38 1074.53,1101.1 1107.56,1101.1 v1(1129.92,1078.74)
  MidLayer4 w5: v1(562.85,699.62) 544.15,680.93 503.81,680.93 458.66,726.07 458.66,1818.5 502.36,1862.2 620.7,1862.2 v1(710.9,1952.4)
  Bottom Layer w5: R15.2@689.74,1978.35 689.74,1962.16 699.5,1952.4 v1(710.9,1952.4)
FPGA_M2: HDR_T1.56 R14.1 | length 2043.1
  Top Layer w5: v2(1972.44,2692.91) v2(2015.75,2692.91)
  Bottom Layer w5: R14.1@732.11,2020.14 757.61,2020.08 788.18,2050.66 788.18,2136.19 808.7,2156.71 894.14,2242.13 954.66,2302.67 969.7,2317.71 1070.87,2418.88 1070.87,2740.55 1149.61,2819.29 1520.47,2819.29 1594.49,2745.28 1983.07,2745.28 2015.75,2712.6 v2(2015.75,2692.91) ; HDR_T1.56@1972.44,2606.3 v2@1972.44,2688.98
FPGA_M2#: R14.2 U4.Y7 | length 2654.9
  Top Layer w5: v1(1248.03,1196.85) U4.Y7@1267.72,1216.54
  MidLayer3 w5: v1@521.52,661.25 v1(520.54,660.26) 556.94,660.26 624.84,728.16 624.84,770.47 799.01,944.64 945.62,944.64 1059.77,1058.78 1177.85,1058.78 1188.67,1069.61 1188.67,1128.65 1197.53,1137.5 1221.14,1137.5 1228.03,1144.39 1228.03,1176.85 v1(1248.03,1196.85)
  MidLayer4 w5: v1(520.54,660.26) 492.98,660.26 437.4,715.85 437.4,1901.97 521.26,1985.83 601.18,1985.83 v1@642.52,2027.17
  Bottom Layer w5: v1(644.6,2027.8) 682.08,2027.8 R14.2@689.74,2020.14
FPGA_PROG_CLK: HDR_T1.88
FPGA_PROG_PWR_ON: HDR_T1.86
FPGA_PROGRAM: HDR_T1.62 R7.1 R10.1 | length 2012.5
  Bottom Layer w5: R10.1@732.1,2103.4 R10.1@732.11,2103.73 732.1,2145.05 732.34,2145.29 769,2145.29 800.42,2176.71 ; 800.43,2176.71 874.14,2250.42 940.52,2316.81 955.55,2331.85 1047.24,2423.54 1047.24,2752.36 1138.98,2844.09 1531.5,2844.09 1610.31,2765.28 2002.44,2765.28 2066.93,2700.79 HDR_T1.62@2066.93,2606.3
FPGA_TCK: HDR_T1.72 R4.1 | length 982.8
  MidLayer3 w5: v1(2127,2128.57) 2149.61,2151.17 2149.61,2216.93 2140.14,2226.39 2140.14,2262.19 2224.41,2346.45 v2(2224.41,2688.98)
  Bottom Layer w5: v1(2127,2128.57) 2185.44,2128.57 2228.57,2171.7 2336.93,2171.7 R4.1@2381.98,2216.76
  Bottom Layer w7.87: HDR_T1.72@2224.41,2606.3 v2(2224.41,2688.98)
FPGA_TDI: HDR_T1.78 R6.1 | length 2213.4
  Bottom Layer w5: R6.1@732.41,2187.02 732.1,2186.71 796.29,2186.71 859.99,2250.42 933.45,2323.89 948.48,2338.92 1035.43,2425.87 1035.43,2759.05 1131.89,2855.51 1535.43,2855.51 1615.67,2775.28 2236.54,2775.28 2318.9,2692.91 HDR_T1.78@2318.9,2606.3
FPGA_TDO: HDR_T1.54 R5.1 R11.1 | length 877
  MidLayer4 w5: v2(1940.94,2665.35) 1942.12,2664.17 2100.79,2664.17 2299.21,2465.75 2299.21,2271.65 2305.7,2265.17 2311.3,2259.57 v1(2311.3,2150.17)
  Bottom Layer w5: R5.1@2283.16,2150.17 v1(2311.3,2150.17) R11.1@2339.56,2150.17
  Bottom Layer w7.87: HDR_T1.54@1940.95,2606.3 v2(1940.94,2665.35)
FPGA_TMS: HDR_T1.70 R3.1 | length 735.9
  MidLayer3 w5: v1(2125,2198) 2118.39,2204.61 2118.39,2263.41 2109.6,2272.2 2109.6,2294.64 2192.91,2377.95 v2(2192.91,2665.35)
  Bottom Layer w5: v1(2125,2198) 2128.2,2194.8 2261.27,2194.8 R3.1@2283.23,2216.76
  Bottom Layer w7.87: HDR_T1.70@2192.91,2606.3 v2(2192.91,2665.35)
